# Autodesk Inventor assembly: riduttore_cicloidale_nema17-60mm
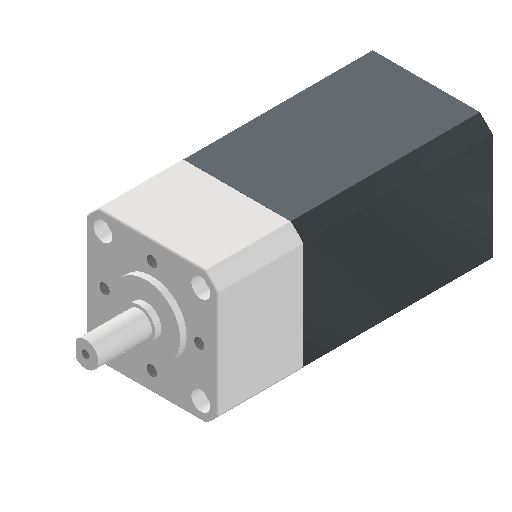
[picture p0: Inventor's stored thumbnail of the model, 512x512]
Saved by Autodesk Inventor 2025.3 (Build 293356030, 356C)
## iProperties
Created: 2026-03
Part Number: riduttore_cicloidale_nema17-60mm
Document SubType Name: Assembly
Designer: R5800u
Author: R5800u
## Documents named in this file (3)
- C:\Users\R5800u\Desktop\robot_riduttore_cicloidale3\Workgroups\NotInProject\riduttore_cicloidale_nema17-60mm.iam
- C:\Users\R5800u\Desktop\robot_riduttore_cicloidale3\Workgroups\NotInProject\riduttore ciccloidale TS42 15-1.ipt
- C:\Users\R5800u\Desktop\robot_riduttore_cicloidale3\Workgroups\NotInProject\NEMA 17 60mm.ipt
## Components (2 placed, 2 different names)
1. NEMA 17 60mm:1 — Coincidente:1, Coincidente:2, Angolo:1
2. riduttore ciccloidale TS42 15-1:1 — Coincidente:1, Coincidente:2, Angolo:1
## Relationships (3: Mate 2, Angle 1)
- Coincidente:1 [Mate]: NEMA 17 60mm:1 ↔ riduttore ciccloidale TS42 15-1:1
- Coincidente:2 [Mate]: NEMA 17 60mm:1 ↔ riduttore ciccloidale TS42 15-1:1
- Angolo:1 [Angle]: NEMA 17 60mm:1 ↔ riduttore ciccloidale TS42 15-1:1
